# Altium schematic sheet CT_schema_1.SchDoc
size 387 x 258 mm
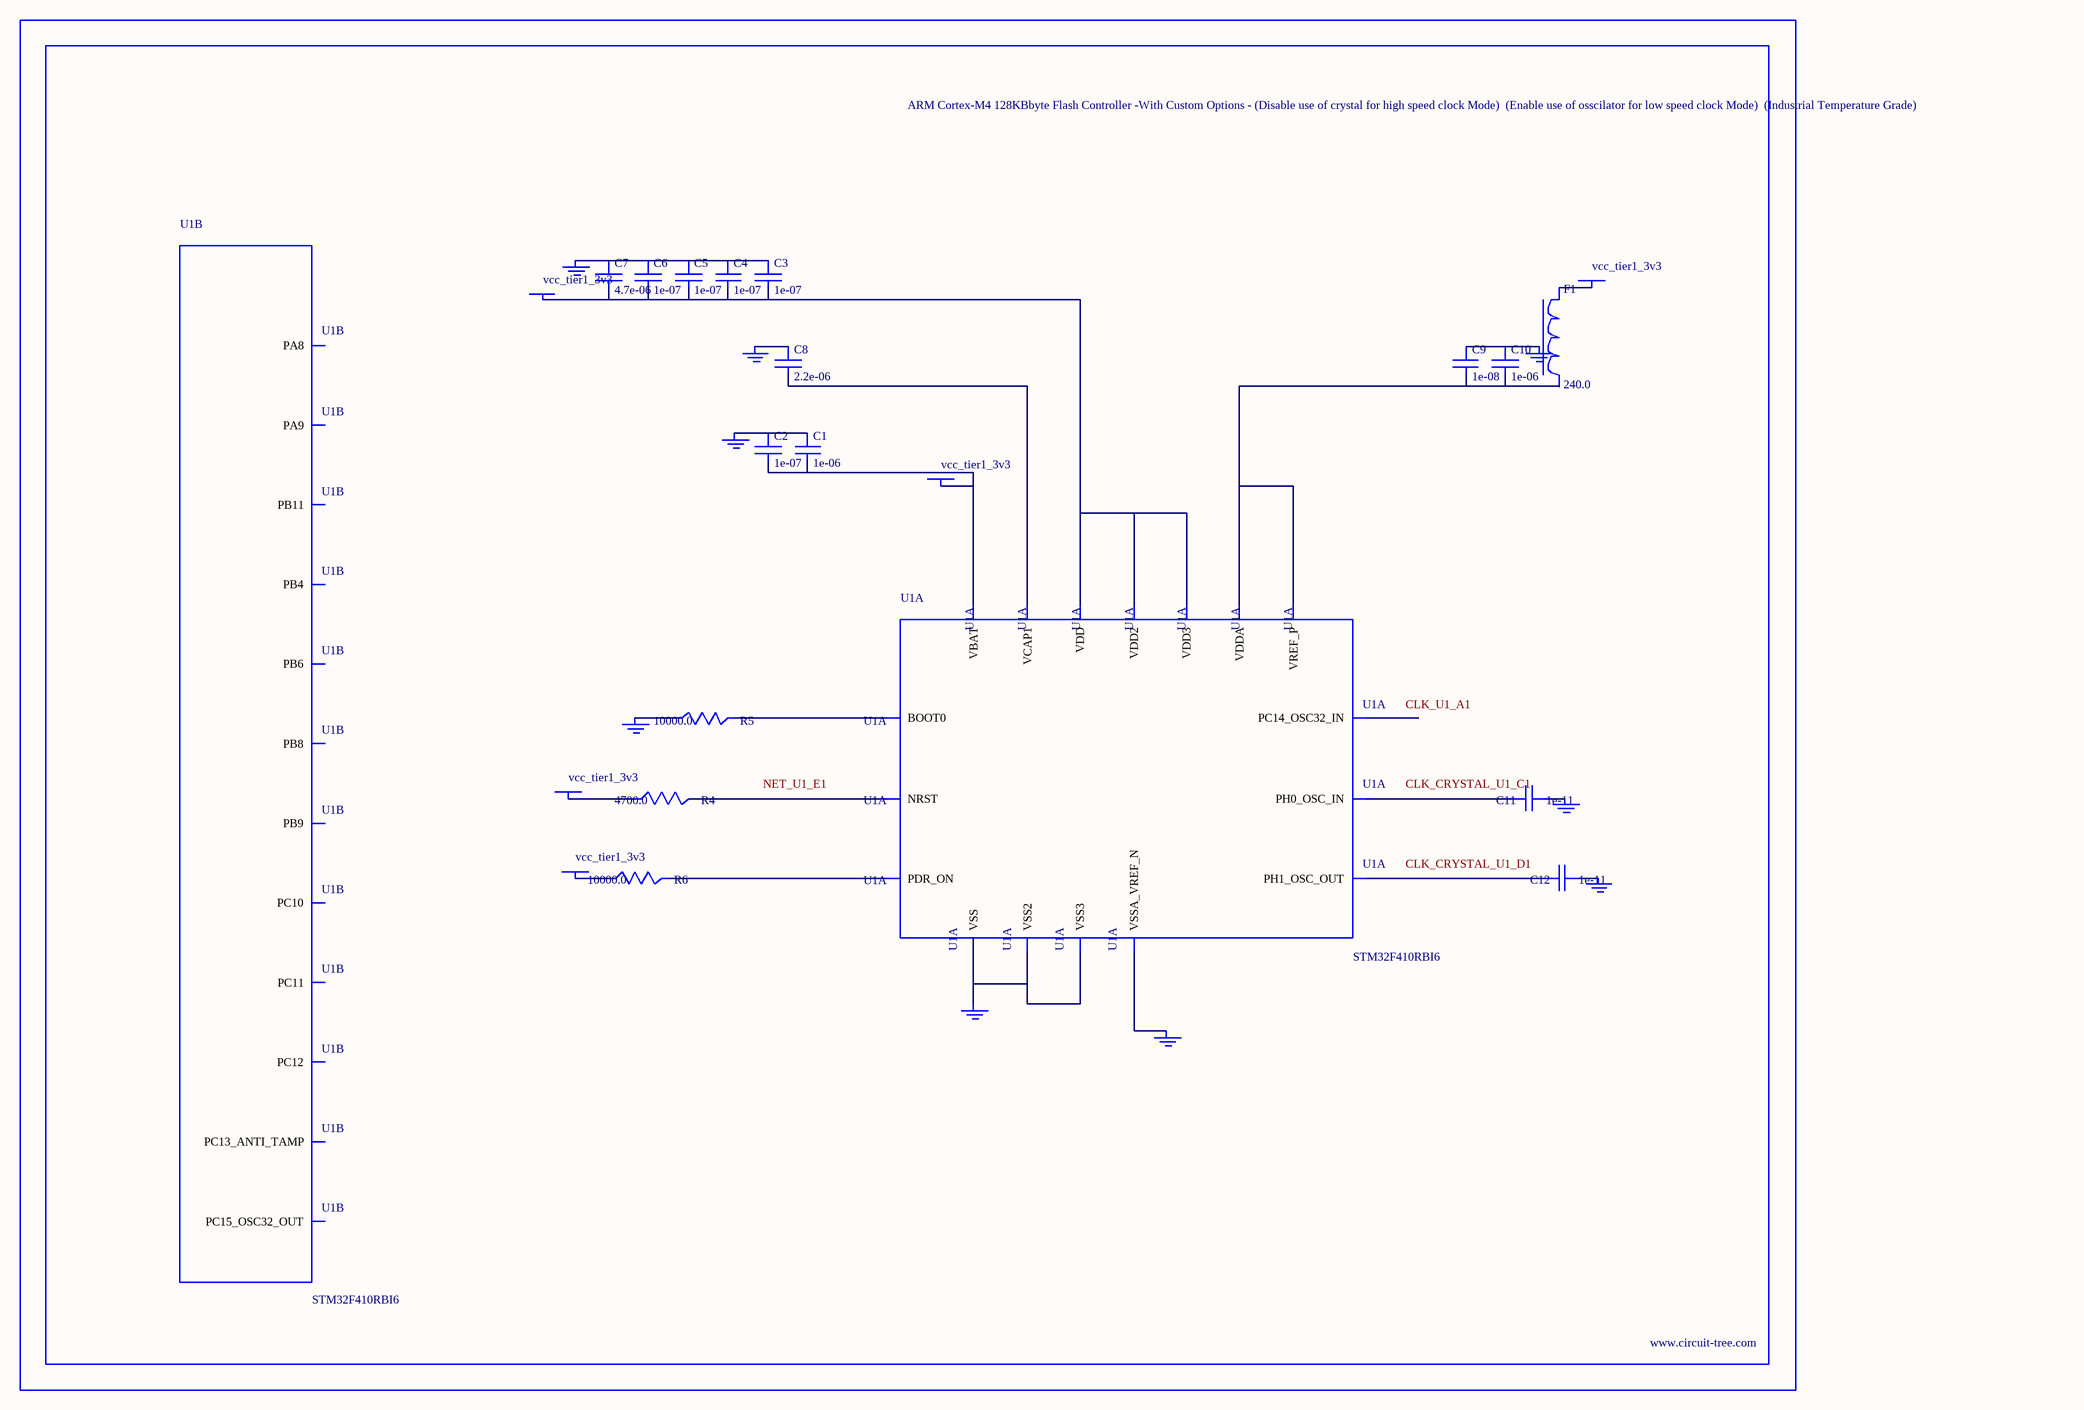
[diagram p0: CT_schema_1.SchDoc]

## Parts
BORDER0  (no value)
C1  1e-06  [C0603]
C2  1e-07  [C0603]
C3  1e-07  [C0603]
C4  1e-07  [C0603]
C5  1e-07  [C0603]
C6  1e-07  [C0603]
C7  4.7e-06  [C0603]
C8  2.2e-06  [C0603]
C9  1e-08  [C0603]
C10  1e-06  [C0603]
C11  1e-11  [C0402]
C12  1e-11  [C0402]
F1  240.0  [L0603]
GND_INSTANCE_0_0  (no value)
GND_INSTANCE_0_1  (no value)
GND_INSTANCE_0_2  (no value)
GND_INSTANCE_0_3  (no value)
GND_INSTANCE_0_4  (no value)
GND_INSTANCE_0_5  (no value)
GND_INSTANCE_0_6  (no value)
GND_INSTANCE_0_7  (no value)
GND_INSTANCE_0_8  (no value)
POWER_INSTANCE_0_0  vcc_tier1_3v3
POWER_INSTANCE_0_1  vcc_tier1_3v3
POWER_INSTANCE_0_2  vcc_tier1_3v3
POWER_INSTANCE_0_3  vcc_tier1_3v3
POWER_INSTANCE_0_4  vcc_tier1_3v3
R4  4700.0  [R0603]
R5  10000.0  [R0603]
R6  10000.0  [R0603]
U1  STM32F410RBI6  [UFBGA64]  (parts A,B of 6)

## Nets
NetC1_1: C1.1 C2.1 GND_INSTANCE_0_0.0(GND)
NetC1_2: C1.2 C2.2 POWER_INSTANCE_0_0.0(PWR) U1.A2(VBAT)
NetC3_1: C3.1 C4.1 C5.1 C6.1 C7.1 GND_INSTANCE_0_2.0(GND)
NetC3_2: C3.2 C4.2 C5.2 C6.2 C7.2 POWER_INSTANCE_0_2.0(PWR) U1.D2(VDD) U1.E4(VDD2) U1.E5(VDD3)
NetC8_1: C8.1 GND_INSTANCE_0_4.0(GND)
NetC8_2: C8.2 U1.H7(VCAP1)
NetC9_1: C9.1 C10.1 GND_INSTANCE_0_1.0(GND)
NetC9_2: C9.2 C10.2 U1.G1(VREF_P) U1.H1(VDDA)
NetC11_1: C11.1 GND_INSTANCE_0_5.0(GND)
NetC11_2: C11.2 U1.C1(PH0_OSC_IN)
NetC12_1: C12.1 GND_INSTANCE_0_6.0(GND)
NetC12_2: C12.2 U1.D1(PH1_OSC_OUT)
NetF1_1: F1.1 POWER_INSTANCE_0_1.0(PWR)
NetGND_INSTANCE_0_3_0: GND_INSTANCE_0_3.0(GND) R5.1
NetGND_INSTANCE_0_7_0: GND_INSTANCE_0_7.0(GND) U1.F1(VSSA_VREF_N)
NetGND_INSTANCE_0_8_0: GND_INSTANCE_0_8.0(GND) U1.C2(VSS) U1.D5(VSS2) U1.D6(VSS3)
NetPOWER_INSTANCE_0_3_0: POWER_INSTANCE_0_3.0(PWR) R6.1
NetPOWER_INSTANCE_0_4_0: POWER_INSTANCE_0_4.0(PWR) R4.1
NetR4_2: R4.2 U1.E1(NRST)
NetR5_2: R5.2 U1.A4(BOOT0)
NetR6_2: R6.2 U1.C3(PDR_ON)

Not connected (* = marked no-connect by the designer): F1 2; U1 A1(PC14_OSC32_IN) A3(PB9) A6(PC12) B1(PC15_OSC32_OUT) B2(PC13_ANTI_TAMP) B3(PB8) B5(PB11) B6(PC11) B8(PA9) C4(PB6) C5(PB4) C6(PC10) C8(PA8)

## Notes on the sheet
- Labels drawn without touching a wire or pin: CLK_CRYSTAL_U1_C1, CLK_CRYSTAL_U1_D1, CLK_U1_A1, NET_U1_E1

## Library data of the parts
BORDER0 = BORDER_PAGE0
C1 C10 = C0603C105K3RACTU
C2-C6 = 06035C104K4Z2A
C7 = GRM188R6YA475KE15D
C8 = C0603C225K8RACTU
C9 = 06035C103K4Z2A
C11 C12 = C0402C100K3GACTU
F1 = Z0603C241ASMST
GND_INSTANCE_0_0-GND_INSTANCE_0_8 = GND
POWER_INSTANCE_0_0-POWER_INSTANCE_0_4 = PWR
R4 = RC0603JR-074K7L
R5 R6 = RC0603JR-0710KL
